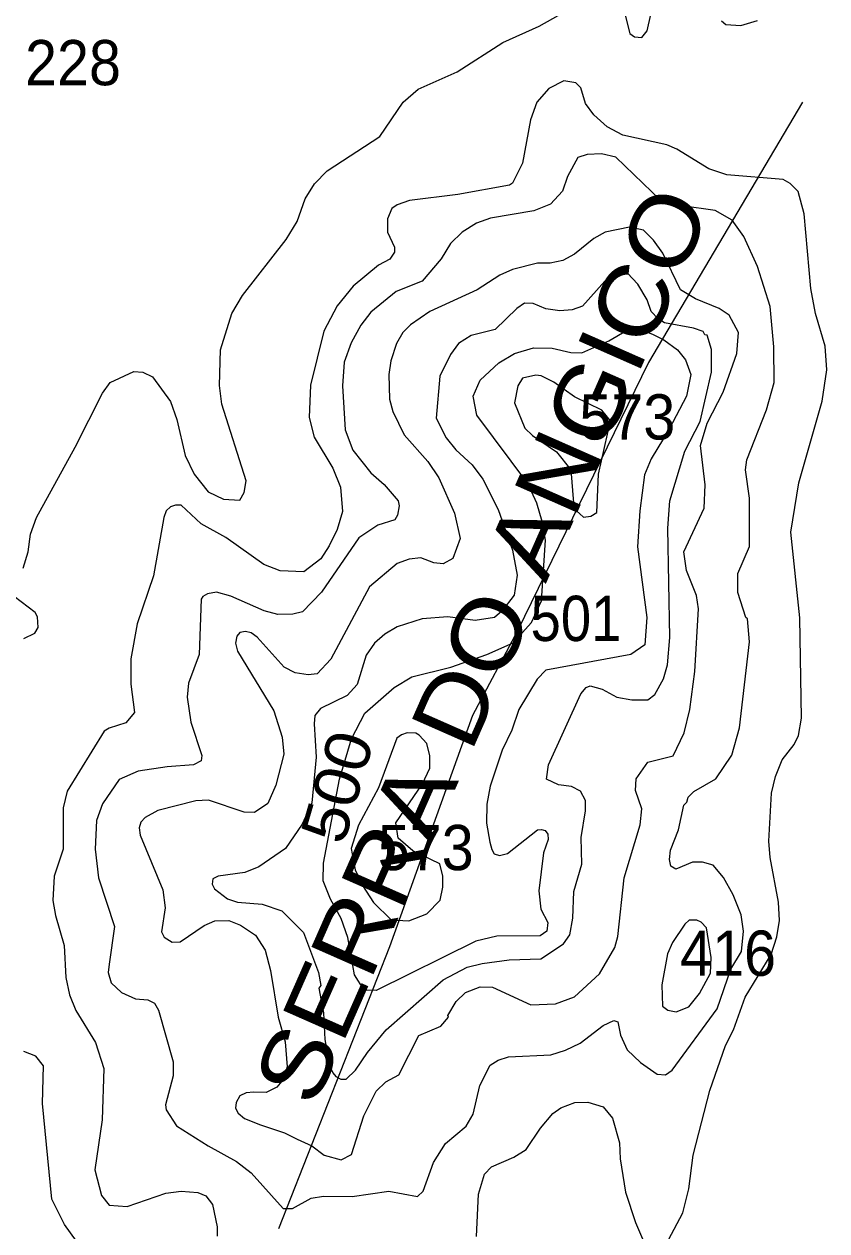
# Model space of a CAD drawing. Extents: x 499.9 to 555.3, y 9281.5 to 9336.8.
# Drawn here: x 526.975 to 529.812, y 9286.554 to 9290.821 of the extents above; entities that cross this region are included whole.
import ezdxf
from ezdxf.enums import TextEntityAlignment as Align

# ---------------------------------------------------------------- set-up
doc = ezdxf.new("R2010")
doc.units = 0
doc.header["$LTSCALE"] = 0.064
for name, color, linetype, lineweight in [('1', 7, 'Continuous', 25), ('2', 7, 'Continuous', 13), ('26', 7, 'Continuous', 25)]:
    doc.layers.add(name, color=color, linetype=linetype, lineweight=lineweight)
doc.layers.add('21', color=7, linetype='Continuous')
doc.layers.add('61', color=7, linetype='Continuous')

msp = doc.modelspace()

# ---------------------------------------------------------------- linework, layer by layer
at = {"layer": '1'}
for points in [[(526.9712, 9288.8983), (526.9891, 9288.9558), (526.9977, 9289.0174), (527.018, 9289.0767), (527.1551, 9289.3254), (527.2517, 9289.5167), (527.2783, 9289.5542), (527.3622, 9289.593), (527.3939, 9289.5911), (527.4281, 9289.5739), (527.4918, 9289.4865), (527.5139, 9289.4236), (527.5445, 9289.2956), (527.5761, 9289.23), (527.6248, 9289.168), (527.679, 9289.1416), (527.7369, 9289.1387), (527.7524, 9289.1653), (527.7591, 9289.2064), (527.674, 9289.4781), (527.6655, 9289.5438), (527.6687, 9289.6703), (527.7085, 9289.7984), (527.7462, 9289.8614), (527.9009, 9290.0596), (527.9395, 9290.124), (527.9684, 9290.2032), (528.0014, 9290.2568), (528.0459, 9290.3029), (528.2319, 9290.4241), (528.3144, 9290.5458), (528.3674, 9290.5909), (528.5056, 9290.6526), (528.6673, 9290.7569), (528.7957, 9290.8148), (528.9778, 9290.9185)], [(529.0954, 9290.8678), (529.1156, 9290.7887), (529.1326, 9290.7769), (529.1578, 9290.7741), (529.1775, 9290.7972), (529.1902, 9290.8552)], [(529.4396, 9290.8337), (529.4555, 9290.8203), (529.5078, 9290.8166), (529.5673, 9290.8347)], [(526.9731, 9288.6496), (527.0121, 9288.6682), (527.0243, 9288.6884), (527.0216, 9288.7251), (527.0131, 9288.7409), (526.9389, 9288.797)], [(527.2503, 9286.3913), (527.1172, 9286.5773), (527.072, 9286.6663), (527.039, 9287.0051), (527.0432, 9287.1378), (527.016, 9287.172), (526.9741, 9287.189)]]:
    msp.add_lwpolyline(points, dxfattribs=at)
msp.add_lwpolyline([(528.704, 9288.634), (528.7681, 9288.7054), (528.8041, 9288.7821), (528.8175, 9288.9972), (528.8066, 9289.0631), (528.7866, 9289.128), (528.7555, 9289.1968), (528.5745, 9289.4388), (528.5619, 9289.5056), (528.5867, 9289.5621), (528.6531, 9289.6243), (528.7088, 9289.6569), (528.7756, 9289.6773), (528.8408, 9289.6759), (528.9076, 9289.6602), (528.9458, 9289.6586), (529.0421, 9289.7015), (529.1047, 9289.7382), (529.1559, 9289.7409), (529.1959, 9289.7252), (529.236, 9289.7052), (529.2846, 9289.6695), (529.3127, 9289.6349), (529.3317, 9289.5823), (529.316, 9289.5065), (529.2546, 9289.3893), (529.1916, 9289.2849), (529.1673, 9289.2277), (529.1516, 9289.1), (529.1425, 9288.9732), (529.1757, 9288.7234), (529.1692, 9288.6264), (529.1199, 9288.593), (528.8195, 9288.5366), (528.7884, 9288.5055), (528.7237, 9288.3983), (528.6983, 9288.3247), (528.665, 9288.2537), (528.6218, 9288.1265), (528.6109, 9288.0636), (528.6094, 9287.996), (528.6206, 9287.9292), (528.628, 9287.9034), (528.6367, 9287.8875), (528.6555, 9287.882), (528.683, 9287.8892), (528.7893, 9287.972), (528.8038, 9287.9742), (528.8171, 9287.97), (528.8263, 9287.9572), (528.8268, 9287.9388), (528.8112, 9287.8909), (528.794, 9287.7573), (528.8018, 9287.6921), (528.8257, 9287.6444), (528.8229, 9287.6145), (528.7986, 9287.5973), (528.6457, 9287.5963), (528.5719, 9287.5784), (528.2191, 9287.404), (528.1766, 9287.4052), (528.1429, 9287.4597), (528.1192, 9287.5917), (528.0954, 9287.6586), (528.0582, 9287.727), (528.0316, 9287.792), (528.0334, 9287.8544), (528.0893, 9288.152), (528.1316, 9288.2943), (528.1787, 9288.3847), (528.283, 9288.4758), (528.3451, 9288.5139), (528.4829, 9288.5474), (528.6104, 9288.5929)], close=True, dxfattribs=at)
at = {"layer": '2'}
for points in [[(529.4826, 9287.2651), (529.5235, 9287.3808), (529.6161, 9287.5318), (529.636, 9287.5941), (529.6452, 9287.6523), (529.6421, 9287.7167), (529.6121, 9287.8751), (529.6072, 9287.9324), (529.6163, 9288.1023), (529.6306, 9288.1608), (529.655, 9288.2196), (529.6974, 9288.2739), (529.7123, 9288.3063), (529.7232, 9288.3676), (529.7169, 9288.7225), (529.6852, 9289.0249), (529.7138, 9289.2), (529.7954, 9289.4883), (529.8125, 9289.5986), (529.8061, 9289.6831), (529.7727, 9289.7985), (529.7564, 9289.8871), (529.7325, 9290.1502), (529.7105, 9290.2296), (529.6825, 9290.2578), (529.658, 9290.2717), (529.4584, 9290.289), (529.395, 9290.3098), (529.2817, 9290.3795), (529.2465, 9290.3949), (529.0917, 9290.4294), (529.036, 9290.4583), (528.9885, 9290.5012), (528.9595, 9290.5404), (528.9425, 9290.5959), (528.9254, 9290.6138), (528.8824, 9290.621), (528.8299, 9290.5937), (528.7869, 9290.5451), (528.7646, 9290.4833), (528.7363, 9290.3293), (528.7015, 9290.2588), (528.6908, 9290.2519), (528.5081, 9290.2188), (528.3371, 9290.1982), (528.2932, 9290.1822), (528.2751, 9290.1691), (528.2591, 9290.1331), (528.2591, 9290.0863), (528.2838, 9290.0325), (528.2842, 9290.0153), (528.2678, 9289.9908), (528.2277, 9289.9694), (528.1377, 9289.895), (528.0809, 9289.8255), (528.0344, 9289.7359), (527.9871, 9289.5445), (527.9822, 9289.43), (528, 9289.361), (528.0665, 9289.2509), (528.0935, 9289.1841), (528.0998, 9289.0981), (528.0808, 9289.0346), (528.0535, 9288.9766), (528.0235, 9288.9311), (527.9639, 9288.885), (527.8796, 9288.8883), (527.8224, 9288.9108), (527.6877, 9289.0058), (527.6009, 9289.0549), (527.5297, 9289.12), (527.5095, 9289.12), (527.4916, 9289.115), (527.4764, 9289.101), (527.4685, 9289.077), (527.4318, 9288.8706), (527.3737, 9288.7014), (527.3522, 9288.5777), (527.3519, 9288.4878), (527.3645, 9288.3876), (527.3337, 9288.3508), (527.2756, 9288.3325), (527.2577, 9288.3209), (527.1263, 9288.1089), (527.1132, 9288.0502), (527.113, 9287.9038), (527.0813, 9287.8083), (527.0766, 9287.7223), (527.0851, 9287.6696), (527.1163, 9287.5639), (527.1226, 9287.4501), (527.1347, 9287.3893), (527.1569, 9287.3333), (527.2274, 9287.2208), (527.2562, 9287.1285)], [(529.4251, 9287.3394), (529.4731, 9287.4797), (529.5107, 9287.5423), (529.518, 9287.6141), (529.5099, 9287.6715), (529.4814, 9287.7421), (529.4471, 9287.8043), (529.4102, 9287.8481), (529.3725, 9287.8583), (529.337, 9287.8582), (529.2783, 9287.8329), (529.2605, 9287.8443), (529.2556, 9287.867), (529.2601, 9287.9008), (529.2877, 9287.973), (529.3066, 9288.0602), (529.3173, 9288.0701), (529.3222, 9288.0883), (529.3422, 9288.1086), (529.4201, 9288.1527), (529.4769, 9288.2362), (529.5039, 9288.3327), (529.5386, 9288.6374), (529.5322, 9288.7186), (529.5261, 9288.7233), (529.4974, 9288.8117), (529.4977, 9288.8792), (529.5385, 9288.9741), (529.5386, 9289.1452), (529.5245, 9289.246), (529.5298, 9289.2811), (529.5991, 9289.4578), (529.6262, 9289.5541), (529.6248, 9289.6808), (529.6119, 9289.8232), (529.567, 9289.9647), (529.5188, 9290.0705), (529.4783, 9290.1278), (529.4177, 9290.1629), (529.3012, 9290.1792), (529.2251, 9290.1975), (529.0659, 9290.3505), (529.0159, 9290.3633), (528.965, 9290.36), (528.9324, 9290.35), (528.8961, 9290.283), (528.8776, 9290.2308), (528.8351, 9290.1854), (528.7771, 9290.1613), (528.6233, 9290.1352), (528.5743, 9290.1182), (528.5234, 9290.0864), (528.4825, 9290.0457), (528.4495, 9289.992), (528.3821, 9289.912), (528.2903, 9289.8759), (528.2002, 9289.8032), (528.1652, 9289.757), (528.1306, 9289.6942), (528.1064, 9289.6265), (528.1001, 9289.5425), (528.1097, 9289.3871), (528.1368, 9289.3151), (528.2003, 9289.2351), (528.2479, 9289.1936), (528.2969, 9289.1363), (528.3002, 9289.1181), (528.2946, 9289.0853), (528.2847, 9289.0686), (528.2255, 9289.0494), (528.1584, 9289.0052), (528.0264, 9288.8134), (527.959, 9288.7432), (527.9248, 9288.7354), (527.872, 9288.7342), (527.8231, 9288.7465), (527.7052, 9288.7989), (527.6551, 9288.813), (527.6226, 9288.8066), (527.6068, 9288.7974), (527.6004, 9288.7886), (527.5937, 9288.5921), (527.556, 9288.491), (527.551, 9288.4411), (527.5644, 9288.3531), (527.6031, 9288.2356), (527.6003, 9288.2163), (527.5729, 9288.202), (527.48, 9288.1958), (527.3781, 9288.1799), (527.3102, 9288.1503), (527.2521, 9288.0641), (527.2309, 9288.0055), (527.2262, 9287.9038), (527.2373, 9287.8026)], [(529.3817, 9289.1919), (529.3659, 9289.3314), (529.3894, 9289.4104), (529.4464, 9289.5201), (529.4944, 9289.657), (529.5003, 9289.7314), (529.4673, 9289.7927), (529.4319, 9289.8158), (529.3481, 9289.85), (529.2956, 9289.8814), (529.2331, 9290.0117), (529.2, 9290.0579), (529.1645, 9290.0926), (529.1146, 9290.1039), (529.0288, 9290.0861), (528.9887, 9290.063), (528.9202, 9290.0075), (528.8791, 9289.9861), (528.8344, 9289.9768), (528.79, 9289.9765), (528.7008, 9289.9541), (528.6564, 9289.9333), (528.5767, 9289.8825), (528.4094, 9289.8052), (528.3403, 9289.7586), (528.3129, 9289.7309), (528.291, 9289.6918), (528.2715, 9289.6311), (528.2636, 9289.5825), (528.2662, 9289.4959), (528.2779, 9289.4515), (528.3178, 9289.3687), (528.4023, 9289.2748), (528.4409, 9289.2177), (528.4962, 9289.0918), (528.5167, 9289.0027), (528.4905, 9288.9321), (528.4566, 9288.9135), (528.4228, 9288.9171), (528.3769, 9288.9339), (528.3363, 9288.9295), (528.2936, 9288.9146), (528.1955, 9288.8322), (528.0585, 9288.5762), (528.0107, 9288.5239), (527.9782, 9288.5206), (527.9328, 9288.5277), (527.8942, 9288.5481), (527.7979, 9288.6536), (527.7773, 9288.6689), (527.7571, 9288.6742), (527.7375, 9288.6697), (527.7264, 9288.6569), (527.7214, 9288.6329), (527.7294, 9288.6041), (527.8571, 9288.3932), (527.8869, 9288.3006), (527.8927, 9288.2403), (527.8643, 9288.1305), (527.8359, 9288.066), (527.7888, 9288.0336), (527.7523, 9288.0354), (527.6264, 9288.0777), (527.5818, 9288.0749), (527.4468, 9288.0409), (527.4026, 9288.0157), (527.3872, 9287.9998), (527.381, 9287.9792), (527.3852, 9287.9532), (527.4649, 9287.7604), (527.4728, 9287.6967), (527.4601, 9287.6119), (527.4695, 9287.5926), (527.4984, 9287.5753), (527.5262, 9287.5767), (527.6114, 9287.6338), (527.6488, 9287.6506), (527.698, 9287.6514), (527.7395, 9287.6358), (527.7926, 9287.6002), (527.8264, 9287.5472), (527.8452, 9287.4748), (527.8722, 9287.31), (527.8976, 9287.2233), (527.904, 9287.135), (527.8916, 9287.0905), (527.8678, 9287.0623), (527.8301, 9287.0438), (527.7863, 9287.0447), (527.7595, 9287.0419), (527.7372, 9287.032), (527.7245, 9287.0088), (527.7213, 9286.9883), (527.731, 9286.9708), (527.7541, 9286.9517)], [(528.9424, 9288.4536), (528.9619, 9288.4762), (528.9757, 9288.4817), (529.0187, 9288.4695), (529.0695, 9288.442), (529.1226, 9288.4318), (529.1795, 9288.4319), (529.2041, 9288.4513), (529.2349, 9288.5069), (529.2492, 9288.5557), (529.2571, 9288.6528), (529.2507, 9289.039), (529.257, 9289.1363), (529.3104, 9289.3119), (529.3646, 9289.4165), (529.405, 9289.5908), (529.405, 9289.6704), (529.3893, 9289.7212), (529.381, 9289.7228), (529.3747, 9289.734), (529.3407, 9289.7467), (529.2383, 9289.7656), (529.2159, 9289.7792), (529.1913, 9289.8053), (529.1775, 9289.8471), (529.1443, 9289.9018), (529.1073, 9289.9414), (529.0772, 9289.954), (529.057, 9289.9453), (528.949, 9289.8238), (528.9116, 9289.8114), (528.8679, 9289.8081), (528.8194, 9289.8145), (528.774, 9289.8334), (528.743, 9289.8347), (528.7159, 9289.8158), (528.6404, 9289.742), (528.5552, 9289.7203), (528.5107, 9289.6917), (528.4824, 9289.6527), (528.4441, 9289.5762), (528.4312, 9289.4277), (528.4666, 9289.3586), (528.5011, 9289.3163), (528.5588, 9289.2629), (528.5965, 9289.2127), (528.6502, 9289.1052), (528.7015, 9288.9613), (528.7172, 9288.8729), (528.7071, 9288.8024), (528.6638, 9288.7455), (528.6378, 9288.7235), (528.5686, 9288.7131), (528.4723, 9288.7256), (528.3814, 9288.7189), (528.2935, 9288.6903), (528.2502, 9288.664), (528.2136, 9288.6323), (528.1841, 9288.5896), (528.1518, 9288.4865), (528.1163, 9288.4479), (528.022, 9288.4019), (528.0028, 9288.3765), (527.9997, 9288.3467), (528.0074, 9288.229), (527.9912, 9288.0684), (527.9579, 9287.9924), (527.8984, 9287.9069), (527.8046, 9287.8413), (527.7553, 9287.8217), (527.6607, 9287.8089), (527.642, 9287.7991), (527.6388, 9287.7808), (527.6471, 9287.7639), (527.6938, 9287.7284), (527.7293, 9287.7166), (527.8166, 9287.7102), (527.8859, 9287.6866), (527.9625, 9287.6089), (528.0155, 9287.4684), (528.0231, 9287.4225), (528.0159, 9287.4125), (528.0329, 9287.3259), (528.0378, 9287.2305), (528.0552, 9287.1351), (528.0663, 9287.1127), (528.0768, 9287.0999), (528.0938, 9287.091), (528.1131, 9287.0905), (528.1459, 9287.1231), (528.1883, 9287.185), (528.2546, 9287.2648), (528.4555, 9287.4417), (528.5407, 9287.4867), (528.5941, 9287.5004)], [(528.0348, 9286.8224), (528.0952, 9286.8057), (528.132, 9286.825), (528.1761, 9286.9616), (528.2195, 9287.0481), (528.2528, 9287.0815), (528.2994, 9287.106), (528.3703, 9287.2449), (528.4481, 9287.2788), (528.4747, 9287.3102), (528.473, 9287.3161), (528.5023, 9287.3658), (528.5355, 9287.3977), (528.587, 9287.4173), (528.6307, 9287.4159), (528.766, 9287.3539), (528.8535, 9287.357), (528.92, 9287.3814), (529.0087, 9287.4637), (529.0633, 9287.5561), (529.0739, 9287.5957), (529.0963, 9287.8026), (529.152, 9287.9901), (529.1583, 9288.047), (529.1363, 9288.1115), (529.1379, 9288.1527), (529.1793, 9288.2114), (529.2689, 9288.2337), (529.3081, 9288.3159), (529.3286, 9288.3979), (529.3462, 9288.5324), (529.3587, 9288.7544), (529.3518, 9288.8007), (529.3157, 9288.8889), (529.3064, 9288.9558), (529.3793, 9289.1104), (529.3817, 9289.1919)], [(528.9147, 9287.6602), (528.9181, 9287.7549), (528.9465, 9287.8512), (528.9435, 9287.9452), (528.959, 9288.0395), (528.9591, 9288.0762), (528.9418, 9288.109), (528.91, 9288.1255), (528.8633, 9288.131), (528.8212, 9288.1516), (528.8281, 9288.2023), (528.9424, 9288.4536)], [(527.2373, 9287.8026), (527.2943, 9287.6306), (527.2756, 9287.4978), (527.2717, 9287.4674), (527.2826, 9287.4312), (527.3186, 9287.397)], [(528.5941, 9287.5004), (528.6888, 9287.5129), (528.8018, 9287.5163), (528.8813, 9287.5689), (528.9042, 9287.6006), (528.9147, 9287.6602)], [(527.3186, 9287.397), (527.3679, 9287.3747), (527.4122, 9287.3711), (527.4356, 9287.3594), (527.4498, 9287.3345), (527.5014, 9287.1525), (527.5013, 9287.1024), (527.4746, 9287.0006), (527.4765, 9286.9824), (527.5128, 9286.9261), (527.6249, 9286.8545), (527.7258, 9286.7994), (527.7768, 9286.7598), (527.89, 9286.6329), (527.9232, 9286.6331), (527.9893, 9286.6695), (528.0332, 9286.6773), (528.1349, 9286.6759), (528.2638, 9286.6948), (528.3653, 9286.6754), (528.385, 9286.6942), (528.4216, 9286.7967), (528.4646, 9286.8631), (528.5378, 9286.9241), (528.562, 9286.9674), (528.5857, 9287.0681), (528.6221, 9287.1403), (528.65, 9287.1576), (528.6865, 9287.1692), (528.8365, 9287.177), (528.8886, 9287.1928), (528.9403, 9287.218), (529.0215, 9287.2804), (529.0594, 9287.2978), (529.0739, 9287.2939), (529.0834, 9287.2464), (529.1065, 9287.1942), (529.1537, 9287.1503), (529.2123, 9287.1085), (529.2425, 9287.1058), (529.2654, 9287.1221), (529.4251, 9287.3394)], [(529.2522, 9286.523), (529.3031, 9286.6185), (529.3251, 9286.7029), (529.3403, 9286.8218), (529.3985, 9287.0507), (529.4541, 9287.2099), (529.4826, 9287.2651)], [(527.2562, 9287.1285), (527.25, 9286.9465), (527.2246, 9286.7698), (527.2482, 9286.6797), (527.2758, 9286.6458), (527.3384, 9286.6409)], [(528.574, 9286.535), (528.5805, 9286.6846), (528.6018, 9286.7554), (528.6273, 9286.781), (528.7054, 9286.8146), (528.7496, 9286.842), (528.7998, 9286.9171), (528.8437, 9286.969), (528.8715, 9286.9899), (528.9221, 9287.0082), (528.9673, 9287.0098), (529.0212, 9286.9932), (529.0543, 9286.9533), (529.08, 9286.8652), (529.0816, 9286.809), (529.1011, 9286.6917), (529.1354, 9286.5836), (529.1673, 9286.5102)], [(527.7541, 9286.9517), (527.8108, 9286.9293), (527.8952, 9286.9007), (527.9401, 9286.8785), (527.9917, 9286.8555), (528.0348, 9286.8224)], [(527.3384, 9286.6409), (527.476, 9286.6872), (527.5302, 9286.6949), (527.589, 9286.6895), (527.6165, 9286.6785), (527.6411, 9286.6476), (527.6572, 9286.5692), (527.6574, 9286.5357)]]:
    msp.add_lwpolyline(points, dxfattribs=at)
for points in [[(529.005, 9289.2307), (529.0474, 9289.4191), (529.0166, 9289.4568), (528.9198, 9289.5035), (528.8469, 9289.556), (528.803, 9289.5775), (528.7842, 9289.5802), (528.7367, 9289.569), (528.7205, 9289.543), (528.7081, 9289.4824), (528.745, 9289.393), (528.7716, 9289.3672), (528.8572, 9289.3085), (528.9079, 9289.2452), (528.9166, 9289.1293), (528.926, 9289.1015), (528.9523, 9289.0777), (528.9775, 9289.0811), (528.9998, 9289.0946)], [(528.2093, 9287.7152), (528.2721, 9287.6544), (528.3342, 9287.6505), (528.3981, 9287.676), (528.4452, 9287.7243), (528.4553, 9287.7698), (528.4554, 9287.8085), (528.4448, 9287.8523), (528.349, 9287.8978), (528.2975, 9287.9428), (528.2882, 9287.9975), (528.3827, 9288.1346), (528.4084, 9288.1911), (528.4086, 9288.2347), (528.3979, 9288.2783), (528.3707, 9288.307), (528.3597, 9288.3148), (528.3292, 9288.3155), (528.3083, 9288.3086), (528.2927, 9288.2965), (528.2271, 9288.1209), (528.1568, 9287.9885), (528.1312, 9287.907), (528.1449, 9287.8316), (528.1706, 9287.776)], [(529.3248, 9287.3461), (529.362, 9287.3935), (529.4013, 9287.4651), (529.404, 9287.5206), (529.3871, 9287.6259), (529.3682, 9287.6465), (529.3525, 9287.653), (529.3256, 9287.6527), (529.31, 9287.6391), (529.2669, 9287.5741), (529.2487, 9287.5335), (529.2296, 9287.4248), (529.2309, 9287.3486), (529.2503, 9287.335), (529.2793, 9287.3287)]]:
    msp.add_lwpolyline(points, close=True, dxfattribs=at)
at = {"layer": '26'}
msp.add_lwpolyline([(529.7267, 9290.546), (529.1817, 9289.6249), (528.7184, 9288.6765), (528.5603, 9288.3767), (528.266, 9287.5592), (527.8735, 9286.5617)], dxfattribs=at)

# ---------------------------------------------------------------- texts
at = {"layer": '21'}
for s, width, p in [('228', 0.95, (526.9779, 9290.6053)), ('573', 0.95, (528.9374, 9289.3526)), ('501', 0.9, (528.765, 9288.6401)), ('573', 0.95, (528.2248, 9287.8298)), ('416', 0.95, (529.2936, 9287.4563))]:
    msp.add_text(s, height=0.16, dxfattribs=dict(at, width=width)).set_placement(p)
at = {"layer": '26', "width": 1.15}
msp.add_text('SERRA DO ANGICO', height=0.24, rotation=66.194, dxfattribs=at).set_placement((528.7026, 9288.5784), align=Align.CENTER)
at = {"layer": '61', "width": 1.1}
msp.add_text('500', height=0.16, rotation=73.794, dxfattribs=at).set_placement((528.1584, 9288.1028), align=Align.CENTER)

doc.saveas('drawing.dxf')
